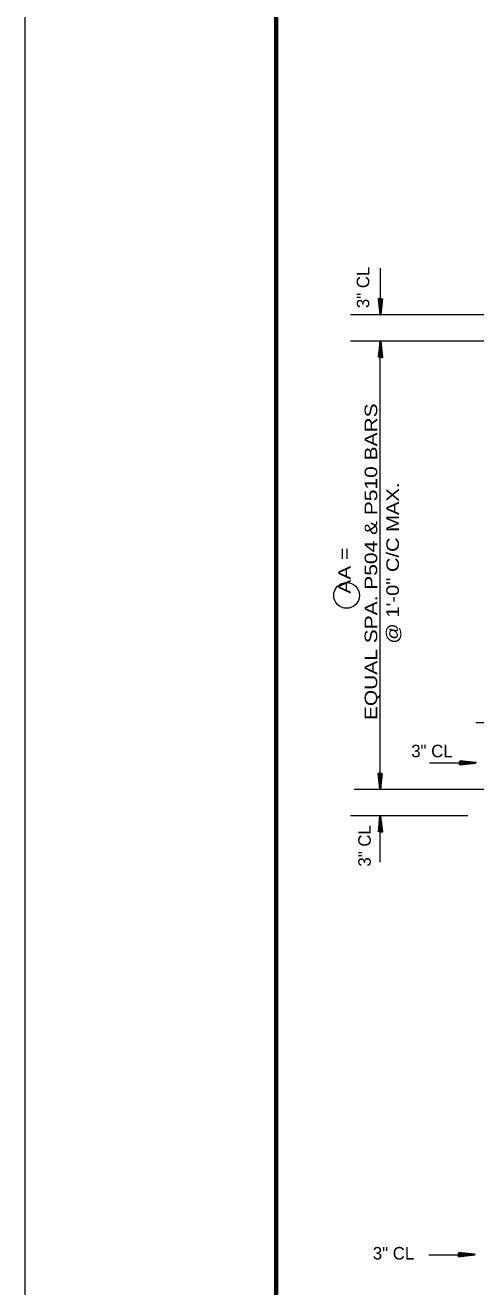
# Model space of a CAD drawing. Extents: x 3.64 to 6.84, y -0.8 to 1.19.
# Drawn here: x 3.645 to 3.944, y -0.372 to 0.467 of the extents above; entities that cross this region are included whole.
import ezdxf
from ezdxf.enums import TextEntityAlignment as Align

# ---------------------------------------------------------------- set-up
doc = ezdxf.new("R2010")
doc.units = 0
doc.header["$LTSCALE"] = 0.0033
doc.layers.add('1', color=7, linetype='Continuous', lineweight=40)

msp = doc.modelspace()

# ---------------------------------------------------------------- linework, layer by layer
at = {"layer": '1', "lineweight": 13}
for p, q in [((3.644833, -0.795833), (3.644833, 1.192417)), ((3.881, 0.284667), (3.881, 0.3055)), ((4.025167, 0.274583), (3.861083, 0.274583)), ((4.038417, 0.256917), (3.861167, 0.256917)), ((3.880917, -0.040667), (3.880917, 0.256083)), ((3.944333, 0.003333), (4.02725, 0.003333)), ((3.913583, -0.023333), (3.934417, -0.023333)), ((4.039167, -0.041083), (3.863583, -0.041083)), ((3.939167, -0.05875), (3.861083, -0.05875)), ((3.880917, -0.0895), (3.880917, -0.068667)), ((3.913083, -0.350667), (3.933917, -0.350667))]:
    msp.add_line(p, q, dxfattribs=at)
at = {"layer": '1', "lineweight": 35}
for p, q in [((3.879917, 0.285), (3.88075, 0.277667)), ((3.880083, 0.285), (3.880833, 0.277667)), ((3.880167, 0.285), (3.881, 0.277667)), ((3.880333, 0.285083), (3.881083, 0.27775)), ((3.881833, 0.285), (3.880833, 0.277167)), ((3.881, 0.28525), (3.881, 0.274667)), ((3.881833, 0.285), (3.881, 0.277167)), ((3.882, 0.285), (3.881083, 0.277167)), ((3.882, 0.285), (3.881083, 0.277167)), ((3.881917, 0.285), (3.881083, 0.277167)), ((3.88, 0.246583), (3.880917, 0.254417)), ((3.88, 0.246583), (3.880917, 0.254417)), ((3.880083, 0.246583), (3.880917, 0.254417)), ((3.880167, 0.246583), (3.881, 0.254417)), ((3.880167, 0.246583), (3.881167, 0.254417)), ((3.881667, 0.2465), (3.880917, 0.253833)), ((3.881, 0.246333), (3.881, 0.256917)), ((3.881833, 0.246583), (3.881, 0.253917)), ((3.881917, 0.246583), (3.881167, 0.253917)), ((3.882083, 0.246583), (3.88125, 0.253917)), ((3.93375, -0.023333), (3.944333, -0.023333)), ((3.933917, -0.024), (3.94125, -0.02325)), ((3.934, -0.022333), (3.941833, -0.02325)), ((3.934, -0.022333), (3.941833, -0.02325)), ((3.934, -0.022417), (3.941833, -0.02325)), ((3.934, -0.0225), (3.941833, -0.023333)), ((3.934, -0.0225), (3.941833, -0.0235)), ((3.934, -0.024167), (3.941333, -0.023333)), ((3.934, -0.02425), (3.941333, -0.0235)), ((3.934, -0.024417), (3.941333, -0.023583)), ((3.879833, -0.030667), (3.880667, -0.038)), ((3.88, -0.030667), (3.88075, -0.038)), ((3.880083, -0.030667), (3.880917, -0.038)), ((3.88025, -0.030583), (3.881, -0.037917)), ((3.88175, -0.030667), (3.88075, -0.0385)), ((3.880917, -0.030417), (3.880917, -0.041)), ((3.88175, -0.030667), (3.880917, -0.0385)), ((3.881917, -0.030667), (3.881, -0.0385)), ((3.881917, -0.030667), (3.881, -0.0385)), ((3.881833, -0.030667), (3.881, -0.0385)), ((3.879917, -0.069083), (3.880833, -0.06125)), ((3.879917, -0.069083), (3.880833, -0.06125)), ((3.88, -0.069083), (3.880833, -0.06125)), ((3.880083, -0.069083), (3.880917, -0.06125)), ((3.880083, -0.069083), (3.881083, -0.06125)), ((3.881583, -0.069167), (3.880833, -0.061833)), ((3.880917, -0.069333), (3.880917, -0.05875)), ((3.88175, -0.069083), (3.880917, -0.06175)), ((3.881833, -0.069083), (3.881083, -0.06175)), ((3.882, -0.069083), (3.881167, -0.06175)), ((3.933, -0.3505), (3.943583, -0.3505)), ((3.933167, -0.351167), (3.9405, -0.350417)), ((3.93325, -0.3495), (3.941083, -0.350417)), ((3.93325, -0.3495), (3.941083, -0.350417)), ((3.93325, -0.349583), (3.941083, -0.350417)), ((3.93325, -0.349667), (3.941083, -0.3505)), ((3.93325, -0.349667), (3.941083, -0.350667)), ((3.93325, -0.351333), (3.940583, -0.3505)), ((3.93325, -0.351417), (3.940583, -0.350667)), ((3.93325, -0.351583), (3.940583, -0.35075))]:
    msp.add_line(p, q, dxfattribs=at)
at = {"layer": '1', "lineweight": 70}
msp.add_lwpolyline([(6.75825, -0.711333), (6.75825, 1.10875), (3.811583, 1.10875), (3.811583, -0.711333)], dxfattribs=at)
at = {"layer": '1', "lineweight": 35}
for points in [[(3.882083, 0.28525), (3.881, 0.274667), (3.879833, 0.28525), (3.881, 0.284667)], [(3.881083, 0.2845), (3.881167, 0.279833), (3.881083, 0.279833), (3.881083, 0.28075), (3.881167, 0.2845), (3.88125, 0.2815), (3.881333, 0.284667), (3.881417, 0.282417), (3.8815, 0.284667), (3.88125, 0.281167), (3.881083, 0.2765), (3.880833, 0.277417), (3.880833, 0.276167), (3.880833, 0.2845), (3.880667, 0.282083), (3.880667, 0.284667), (3.881083, 0.279333), (3.880417, 0.284667)], [(3.879917, 0.246333), (3.881, 0.256917), (3.882167, 0.246333), (3.881, 0.246917)], [(3.880917, 0.247083), (3.880833, 0.25175), (3.880917, 0.25175), (3.880917, 0.250833), (3.880833, 0.247083), (3.88075, 0.250083), (3.880667, 0.246917), (3.880583, 0.249167), (3.8805, 0.246917), (3.88075, 0.250417), (3.880917, 0.255083), (3.881167, 0.254167), (3.881167, 0.255417), (3.881167, 0.247083), (3.881333, 0.2495), (3.881333, 0.246917), (3.880917, 0.25225), (3.881583, 0.246917)], [(3.93375, -0.02225), (3.944333, -0.023333), (3.93375, -0.0245), (3.934333, -0.023333)], [(3.9345, -0.02325), (3.939167, -0.023167), (3.939167, -0.02325), (3.93825, -0.02325), (3.9345, -0.023167), (3.9375, -0.023083), (3.934333, -0.023), (3.936583, -0.022917), (3.934333, -0.022833), (3.937833, -0.023083), (3.9425, -0.02325), (3.941583, -0.0235), (3.942833, -0.0235), (3.9345, -0.0235), (3.936917, -0.023667), (3.934333, -0.023667), (3.939667, -0.02325), (3.934333, -0.023917)], [(3.882, -0.030417), (3.880917, -0.041), (3.87975, -0.030417), (3.880917, -0.031)], [(3.881, -0.031167), (3.881083, -0.035833), (3.881, -0.035833), (3.881, -0.034917), (3.881083, -0.031167), (3.881167, -0.034167), (3.88125, -0.031), (3.881333, -0.03325), (3.881417, -0.031), (3.881167, -0.0345), (3.881, -0.039167), (3.88075, -0.03825), (3.88075, -0.0395), (3.88075, -0.031167), (3.880583, -0.033583), (3.880583, -0.031), (3.881, -0.036333), (3.880333, -0.031)], [(3.879833, -0.069333), (3.880917, -0.05875), (3.882083, -0.069333), (3.880917, -0.06875)], [(3.880833, -0.068583), (3.88075, -0.063917), (3.880833, -0.063917), (3.880833, -0.064833), (3.88075, -0.068583), (3.880667, -0.065583), (3.880583, -0.06875), (3.8805, -0.0665), (3.880417, -0.06875), (3.880667, -0.06525), (3.880833, -0.060583), (3.881083, -0.0615), (3.881083, -0.06025), (3.881083, -0.068583), (3.88125, -0.066167), (3.88125, -0.06875), (3.880833, -0.063417), (3.8815, -0.06875)], [(3.933, -0.349417), (3.943583, -0.3505), (3.933, -0.351667), (3.933583, -0.3505)], [(3.93375, -0.350417), (3.938417, -0.350333), (3.938417, -0.350417), (3.9375, -0.350417), (3.93375, -0.350333), (3.93675, -0.35025), (3.933583, -0.350167), (3.935833, -0.350083), (3.933583, -0.35), (3.937083, -0.35025), (3.94175, -0.350417), (3.940833, -0.350667), (3.942083, -0.350667), (3.93375, -0.350667), (3.936167, -0.350833), (3.933583, -0.350833), (3.938917, -0.350417), (3.933583, -0.351083)]]:
    msp.add_lwpolyline(points, close=True, dxfattribs=at)
for points in [[(3.881083, 0.2845), (3.881833, 0.284917), (3.881583, 0.284667), (3.88125, 0.2845), (3.881333, 0.28425), (3.881667, 0.284417), (3.880917, 0.284583), (3.880417, 0.28475), (3.88, 0.285)], [(3.880917, 0.247083), (3.880167, 0.246667), (3.880417, 0.246917), (3.88075, 0.247083), (3.880667, 0.247333), (3.880333, 0.247167), (3.881083, 0.247), (3.881583, 0.246833), (3.882, 0.246583)], [(3.9345, -0.02325), (3.934083, -0.0225), (3.934333, -0.02275), (3.9345, -0.023083), (3.93475, -0.023), (3.934583, -0.022667), (3.934417, -0.023417), (3.93425, -0.023917), (3.934, -0.024333)], [(3.881, -0.031167), (3.88175, -0.03075), (3.8815, -0.031), (3.881167, -0.031167), (3.88125, -0.031417), (3.881583, -0.03125), (3.880833, -0.031083), (3.880333, -0.030917), (3.879917, -0.030667)], [(3.880833, -0.068583), (3.880083, -0.069), (3.880333, -0.06875), (3.880667, -0.068583), (3.880583, -0.068333), (3.88025, -0.0685), (3.881, -0.068667), (3.8815, -0.068833), (3.881917, -0.069083)], [(3.93375, -0.350417), (3.933333, -0.349667), (3.933583, -0.349917), (3.93375, -0.35025), (3.934, -0.350167), (3.933833, -0.349833), (3.933667, -0.350583), (3.9335, -0.351083), (3.93325, -0.3515)]]:
    msp.add_lwpolyline(points, dxfattribs=at)
at = {"layer": '1', "lineweight": 13}
msp.add_circle((3.8585, 0.087917), 0.008584, dxfattribs=at)

# ---------------------------------------------------------------- texts
at = {"layer": '1'}
for p in [(3.873583, 0.279), (3.874583, -0.092417)]:
    msp.add_text('3" CL', height=0.008334, rotation=90, dxfattribs=at).set_placement(p)
for s, width, p in [('EQUAL SPA. P504 & P510 BARS', 1.25, (3.878833, 0.005)), ('@ 1\'-0" C/C MAX.', 1.2, (3.89325, 0.055833))]:
    msp.add_text(s, height=0.008334, rotation=90, dxfattribs=dict(at, width=width)).set_placement(p)
at = {"layer": '1', "width": 1.25}
msp.add_text('AA =      ', height=0.008334, rotation=90, dxfattribs=at).set_placement((3.86125, 0.115958), align=Align.CENTER)
at = {"layer": '1'}
for p in [(3.9015, -0.01975), (3.875917, -0.35375)]:
    msp.add_text('3" CL', height=0.008334, dxfattribs=at).set_placement(p)

doc.saveas('drawing.dxf')
